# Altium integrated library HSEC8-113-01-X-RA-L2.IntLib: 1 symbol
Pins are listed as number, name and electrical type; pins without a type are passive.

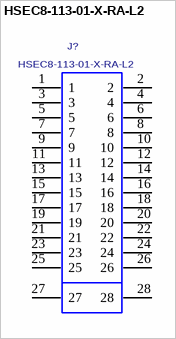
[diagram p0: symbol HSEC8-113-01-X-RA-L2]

## HSEC8-113-01-X-RA-L2
designator J?
0.8MM HIGH SPEED ASSEMBLY, 26 PINS.; MANUFACTURER: SAMTEC
footprint HSEC8-113-01-X-RA-L2
pins: 1, 2, 3, 4, 5, 6, 7, 8, 9, 10, 11, 12, 13, 14, 15, 16, 17, 18, 19, 20, 21, 22, 23, 24, 25, 26, 27, 28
